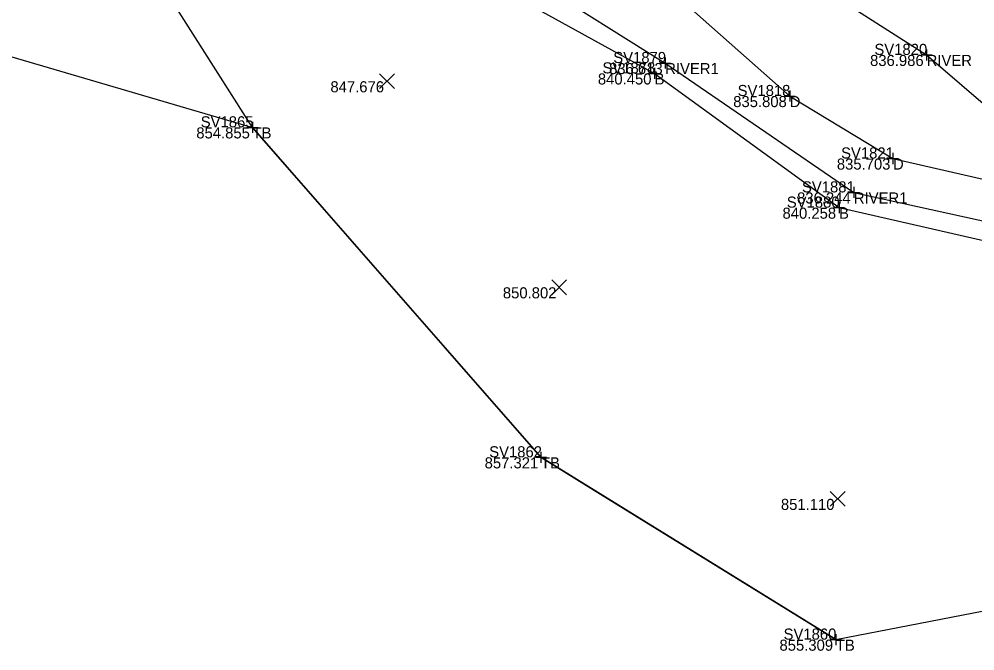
# Model space of a CAD drawing. Extents: x 2125299 to 2129212, y 713100 to 714300.
# Drawn here: x 2127717.6 to 2127803.8, y 713552 to 713609 of the extents above; entities that cross this region are included whole.
import ezdxf

# ---------------------------------------------------------------- set-up
doc = ezdxf.new("R2010")
doc.units = 0
for name, color, linetype in [('DR_X_Ditch', 7, 'Continuous'), ('DT_X_Terrain_Boundary', 7, 'Continuous'), ('HY_X_Water_Edge', 7, 'Continuous'), ('RW_P_Esmt_TMP', 7, 'Continuous'), ('RW_X_Esmt_CH', 7, 'Continuous'), ('RW_X_Fee_WL', 7, 'Continuous'), ('SV_X_Break_Lines', 7, 'Continuous'), ('SV_X_Mon_Cells_Found', 7, 'Continuous'), ('SV_X_Text_Elevation', 7, 'Continuous'), ('SV_X_Top_of_Bank', 7, 'Continuous')]:
    doc.layers.add(name, color=color, linetype=linetype)

msp = doc.modelspace()

# ---------------------------------------------------------------- linework, layer by layer
at = {"layer": 'DR_X_Ditch'}
msp.add_lwpolyline([(2127754.532, 713650.693), (2127755.508, 713649.81), (2127761.022, 713641.797), (2127767.377, 713629.627), (2127773.825, 713613.836), (2127787.097, 713602.059), (2127796.409, 713596.425), (2127812.41, 713592.759), (2127822.136, 713591.387), (2127830.865, 713593.325), (2127835.513, 713593.154), (2127840.963, 713588.862), (2127844.441, 713576.862)], dxfattribs=at)
at = {"layer": 'DT_X_Terrain_Boundary'}
msp.add_lwpolyline([(2127597.812, 713640.572), (2127738.638, 713599.234), (2127748.233, 713588.264), (2127764.66, 713569.482), (2127770.034, 713566.161), (2127791.255, 713553.043), (2127836.751, 713561.853), (2127847.251, 713559.158), (2127863.154, 713564.296), (2127870.027, 713571.542), (2127876.907, 713578.795), (2127883.564, 713586.256), (2127890.206, 713593.73), (2127896.658, 713601.369), (2127903.1, 713609.018), (2127909.489, 713616.71)], dxfattribs=at)
at = {"layer": 'HY_X_Water_Edge'}
for points in [[(2127760.756, 713650.39), (2127768.145, 713637.253), (2127774.726, 713633.042), (2127778.539, 713623.49), (2127790.379, 713611.577), (2127799.446, 713605.767), (2127811.759, 713595.2), (2127821.632, 713592.889), (2127831.559, 713597.952), (2127834.894, 713597.211), (2127837.24, 713606.78), (2127846.533, 713615.952), (2127858.456, 713615.157), (2127864.185, 713615.01), (2127868.763, 713619.475), (2127877.26, 713624.249)], [(2127759.038, 713637.436), (2127761.132, 713628.448), (2127763.153, 713621.237), (2127764.162, 713612.401), (2127775.864, 713605.035), (2127792.881, 713593.368), (2127809.847, 713589.645), (2127822.201, 713590.682), (2127831.261, 713591.73)]]:
    msp.add_lwpolyline(points, dxfattribs=at)
at = {"layer": 'SV_X_Break_Lines'}
msp.add_lwpolyline([(2127735.752, 713636.66), (2127746.037, 713632.28), (2127758.511, 713628.179), (2127762.631, 713621.236), (2127762.072, 713611.189), (2127774.904, 713604.099), (2127791.545, 713591.996), (2127809.166, 713587.988), (2127822.854, 713589.107), (2127830.592, 713589.805), (2127834.63, 713588.796)], dxfattribs=at)
at = {"layer": 'SV_X_Mon_Cells_Found'}
for p, q in [((2127799.446, 713606.267), (2127799.446, 713605.267)), ((2127775.864, 713605.535), (2127775.864, 713604.535)), ((2127798.946, 713605.767), (2127799.946, 713605.767)), ((2127799.446, 713605.767), (2127799.446, 713605.767)), ((2127774.904, 713604.599), (2127774.904, 713603.599)), ((2127775.364, 713605.035), (2127776.364, 713605.035)), ((2127775.864, 713605.035), (2127775.864, 713605.035)), ((2127774.404, 713604.099), (2127775.404, 713604.099)), ((2127774.904, 713604.099), (2127774.904, 713604.099)), ((2127787.097, 713602.559), (2127787.097, 713601.559)), ((2127786.597, 713602.059), (2127787.597, 713602.059)), ((2127787.097, 713602.059), (2127787.097, 713602.059)), ((2127738.138, 713599.234), (2127739.138, 713599.234)), ((2127738.638, 713599.734), (2127738.638, 713598.734)), ((2127738.638, 713599.234), (2127738.638, 713599.234)), ((2127796.409, 713596.925), (2127796.409, 713595.925)), ((2127795.909, 713596.425), (2127796.909, 713596.425)), ((2127796.409, 713596.425), (2127796.409, 713596.425)), ((2127792.881, 713593.868), (2127792.881, 713592.868)), ((2127792.381, 713593.368), (2127793.381, 713593.368)), ((2127792.881, 713593.368), (2127792.881, 713593.368)), ((2127791.545, 713592.496), (2127791.545, 713591.496)), ((2127791.045, 713591.996), (2127792.045, 713591.996)), ((2127791.545, 713591.996), (2127791.545, 713591.996)), ((2127764.66, 713569.982), (2127764.66, 713568.982)), ((2127764.16, 713569.482), (2127765.16, 713569.482)), ((2127764.66, 713569.482), (2127764.66, 713569.482)), ((2127791.255, 713553.543), (2127791.255, 713552.543)), ((2127790.755, 713553.043), (2127791.755, 713553.043)), ((2127791.255, 713553.043), (2127791.255, 713553.043))]:
    msp.add_line(p, q, dxfattribs=at)
at = {"layer": 'SV_X_Text_Elevation'}
for p, q in [((2127750.103, 713602.725), (2127751.437, 713604.06)), ((2127750.103, 713604.06), (2127751.437, 713602.725)), ((2127765.625, 713584.147), (2127766.959, 713585.482)), ((2127765.625, 713585.482), (2127766.959, 713584.147)), ((2127790.748, 713565.07), (2127792.082, 713566.405)), ((2127790.748, 713566.405), (2127792.082, 713565.07))]:
    msp.add_line(p, q, dxfattribs=at)
at = {"layer": 'SV_X_Top_of_Bank'}
msp.add_lwpolyline([(2127791.255, 713553.043), (2127764.66, 713569.482), (2127738.638, 713599.234), (2127728.152, 713615.742), (2127715.103, 713635.711)], dxfattribs=at)

# ---------------------------------------------------------------- texts
at = {"layer": 'RW_P_Esmt_TMP'}
for s, p in [('RIVER', (2127799.446, 713604.767)), ('RIVER1', (2127775.864, 713604.035)), ('B', (2127774.904, 713603.099)), ('D', (2127787.097, 713601.059)), ('TB', (2127738.638, 713598.234)), ('D', (2127796.409, 713595.425)), ('RIVER1', (2127792.881, 713592.368)), ('B', (2127791.545, 713590.996)), ('TB', (2127764.66, 713568.483)), ('TB', (2127791.255, 713552.043))]:
    msp.add_text(s, height=1, dxfattribs=at).set_placement(p)
at = {"layer": 'RW_X_Esmt_CH'}
for s, p in [('SV1879', (2127771.182, 713605.035)), ('SV1820', (2127794.734, 713605.767)), ('SV1878', (2127770.205, 713604.099)), ('SV1818', (2127782.398, 713602.059)), ('SV1865', (2127733.969, 713599.234)), ('SV1821', (2127791.729, 713596.425)), ('SV1881', (2127788.201, 713593.368)), ('SV1880', (2127786.833, 713591.996)), ('SV1862', (2127759.989, 713569.482)), ('SV1860', (2127786.543, 713553.043))]:
    msp.add_text(s, height=1, dxfattribs=at).set_placement(p)
at = {"layer": 'RW_X_Fee_WL'}
for s, p in [('836.986', (2127794.342, 713604.767)), ('836.613', (2127770.8, 713604.035)), ('847.676', (2127745.666, 713602.393)), ('840.450', (2127769.79, 713603.099)), ('835.808', (2127781.997, 713601.059)), ('854.855', (2127733.568, 713598.234)), ('835.703', (2127791.345, 713595.425)), ('836.244', (2127787.759, 713592.368)), ('840.258', (2127786.445, 713590.996)), ('850.802', (2127761.219, 713583.815)), ('857.321', (2127759.578, 713568.483)), ('851.110', (2127786.301, 713564.738)), ('855.309', (2127786.171, 713552.043))]:
    msp.add_text(s, height=1, dxfattribs=at).set_placement(p)

doc.saveas('drawing.dxf')
